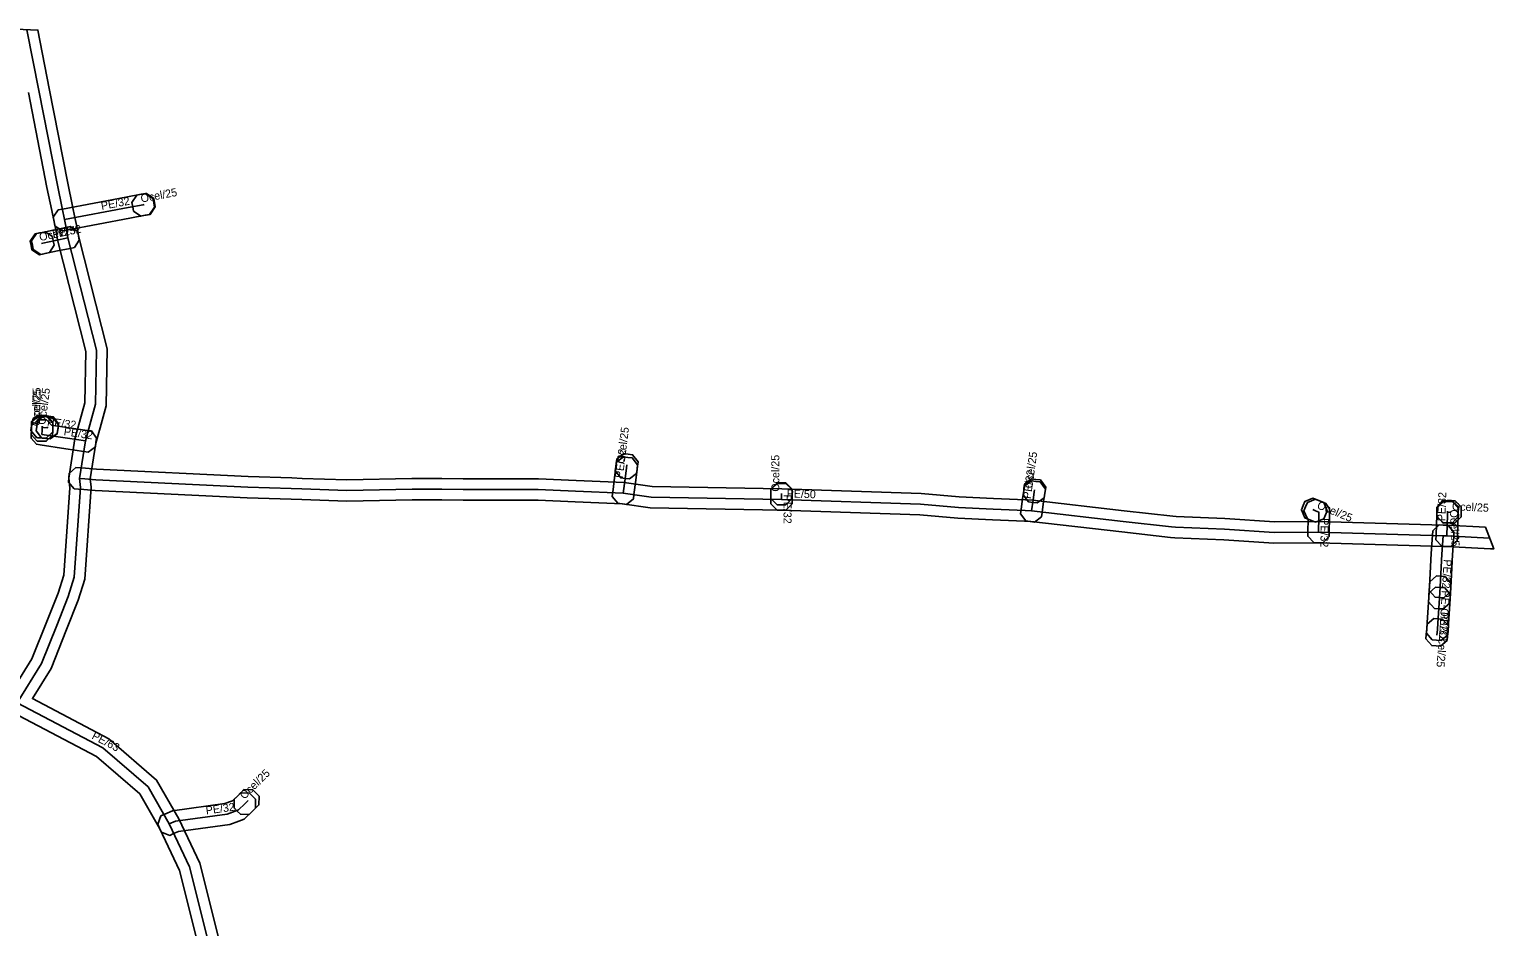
# Model space of a CAD drawing. Extents: x -678368 to -678136, y -1057358 to -1057053.
# Drawn here: x -678273.5 to -678136.2, y -1057136.9 to -1057052.8 of the extents above; entities that cross this region are included whole.
import ezdxf

# ---------------------------------------------------------------- set-up
doc = ezdxf.new("R2010")
doc.units = 0
for name, color, linetype in [('1', 7, 'Continuous'), ('24', 7, 'Continuous'), ('28', 7, 'Continuous'), ('30', 7, 'Continuous')]:
    doc.layers.add(name, color=color, linetype=linetype)

msp = doc.modelspace()

# ---------------------------------------------------------------- linework, layer by layer
at = {"layer": '1'}
for points in [[(-678274.76, -1057052.79), (-678272.71, -1057052.87), (-678271.64, -1057058.33), (-678269.9, -1057067.22), (-678269.45, -1057069.36), (-678269.23, -1057070.42), (-678268.99, -1057071.55), (-678268.91, -1057072.16), (-678266.21, -1057082.76), (-678266.31, -1057088.09), (-678266.88, -1057090.14), (-678267.27, -1057091.59), (-678267.8, -1057094.94), (-678267.72, -1057095.73), (-678268.31, -1057104.33), (-678268.92, -1057106.31), (-678270.01, -1057109.06), (-678271.47, -1057112.71), (-678273.22, -1057115.53), (-678266.06, -1057119.31), (-678261.58, -1057123.18), (-678259.5, -1057126.82), (-678257.54, -1057130.97), (-678255.66, -1057138.42)], [(-678275.49, -1057115.39), (-678273.27, -1057111.81), (-678271.87, -1057108.32), (-678270.8, -1057105.65), (-678270.29, -1057103.97), (-678269.72, -1057095.77), (-678269.82, -1057094.88), (-678269.23, -1057091.17), (-678268.8, -1057089.61), (-678268.31, -1057087.8), (-678268.21, -1057083), (-678270.87, -1057072.54), (-678270.96, -1057071.89), (-678271.19, -1057070.83), (-678271.41, -1057069.77), (-678271.86, -1057067.62), (-678273.6, -1057058.71)], [(-678257.62, -1057138.86), (-678259.44, -1057131.65), (-678261.28, -1057127.74), (-678263.14, -1057124.47), (-678267.2, -1057120.97), (-678275.11, -1057116.8)]]:
    msp.add_lwpolyline(points, dxfattribs=at)
for points in [[(-678262.25, -1057070.15), (-678262.65, -1057070.23), (-678264.08, -1057070.49), (-678270.03, -1057071.61), (-678270.43, -1057071.69), (-678271.11, -1057071.22), (-678271.19, -1057070.81), (-678271.27, -1057070.4), (-678270.8, -1057069.72), (-678270.39, -1057069.64), (-678264.45, -1057068.53), (-678263.02, -1057068.26), (-678262.61, -1057068.18), (-678261.93, -1057068.65), (-678261.85, -1057069.06), (-678261.78, -1057069.47)], [(-678263.43, -1057068.34), (-678263.02, -1057068.26), (-678262.94, -1057068.25), (-678262.54, -1057068.17), (-678261.85, -1057068.64), (-678261.78, -1057069.04), (-678261.7, -1057069.45), (-678262.17, -1057070.14), (-678262.57, -1057070.21), (-678262.65, -1057070.23), (-678263.06, -1057070.3), (-678263.74, -1057069.83), (-678263.82, -1057069.43), (-678263.9, -1057069.02)], [(-678271.63, -1057073.73), (-678272.04, -1057073.81), (-678272.16, -1057073.84), (-678272.57, -1057073.92), (-678273.26, -1057073.47), (-678273.34, -1057073.06), (-678273.43, -1057072.66), (-678272.97, -1057071.97), (-678272.57, -1057071.88), (-678272.44, -1057071.86), (-678272.04, -1057071.77), (-678271.34, -1057072.23), (-678271.26, -1057072.63), (-678271.18, -1057073.04)], [(-678269.28, -1057073.25), (-678269.69, -1057073.33), (-678270.87, -1057073.57), (-678272.04, -1057073.81), (-678272.44, -1057073.9), (-678273.14, -1057073.44), (-678273.22, -1057073.04), (-678273.3, -1057072.63), (-678272.85, -1057071.94), (-678272.44, -1057071.86), (-678271.28, -1057071.61), (-678270.09, -1057071.37), (-678269.69, -1057071.29), (-678268.99, -1057071.74), (-678268.91, -1057072.15), (-678268.83, -1057072.55)], [(-678272.2, -1057089.11), (-678272.09, -1057089.12), (-678272.07, -1057089.1), (-678271.66, -1057089.17), (-678271.25, -1057089.24), (-678270.77, -1057089.91), (-678270.84, -1057090.32), (-678270.84, -1057090.33), (-678270.91, -1057090.72), (-678271.55, -1057091.2), (-678271.95, -1057091.15), (-678272.31, -1057091.11), (-678272.43, -1057091.09), (-678272.84, -1057091.05), (-678273.36, -1057090.39), (-678273.31, -1057089.98), (-678273.26, -1057089.57), (-678272.61, -1057089.06)], [(-678271.89, -1057089.4), (-678271.42, -1057089.9), (-678269.79, -1057090.14), (-678268.1, -1057090.39), (-678267.69, -1057090.45), (-678267.2, -1057091.12), (-678267.26, -1057091.53), (-678267.32, -1057091.94), (-678267.99, -1057092.43), (-678268.4, -1057092.37), (-678270.09, -1057092.12), (-678272.48, -1057091.76), (-678272.85, -1057091.7), (-678273.34, -1057091.13), (-678273.33, -1057090.75), (-678273.32, -1057090.37), (-678273.31, -1057089.96), (-678272.71, -1057089.39), (-678272.3, -1057089.4)], [(-678273.33, -1057090.78), (-678273.32, -1057090.37), (-678273.32, -1057090.08), (-678273.31, -1057089.66), (-678272.7, -1057089.09), (-678272.29, -1057089.1), (-678271.88, -1057089.11), (-678271.31, -1057089.71), (-678271.32, -1057090.13), (-678271.32, -1057090.42), (-678271.33, -1057090.83), (-678271.93, -1057091.41), (-678272.35, -1057091.4), (-678272.76, -1057091.39)], [(-678273.32, -1057090.5), (-678273.32, -1057090.08), (-678273.31, -1057089.97), (-678273.31, -1057089.56), (-678272.71, -1057088.98), (-678272.3, -1057088.99), (-678271.88, -1057089), (-678271.31, -1057089.59), (-678271.31, -1057090.01), (-678271.32, -1057090.12), (-678271.32, -1057090.53), (-678271.92, -1057091.11), (-678272.33, -1057091.1), (-678272.75, -1057091.09)], [(-678272.87, -1057090.43), (-678272.82, -1057090.02), (-678272.8, -1057089.92), (-678272.75, -1057089.51), (-678272.09, -1057089.01), (-678271.68, -1057089.06), (-678271.27, -1057089.12), (-678270.76, -1057089.77), (-678270.82, -1057090.19), (-678270.83, -1057090.29), (-678270.89, -1057090.7), (-678271.55, -1057091.2), (-678271.96, -1057091.15), (-678272.37, -1057091.09)], [(-678216.49, -1057093.62), (-678216.54, -1057094.03), (-678216.67, -1057095.07), (-678216.84, -1057096.41), (-678216.89, -1057096.82), (-678217.54, -1057097.33), (-678217.95, -1057097.28), (-678218.36, -1057097.23), (-678218.87, -1057096.58), (-678218.82, -1057096.17), (-678218.66, -1057094.83), (-678218.53, -1057093.78), (-678218.48, -1057093.37), (-678217.82, -1057092.86), (-678217.41, -1057092.92), (-678217, -1057092.97)], [(-678218.58, -1057094.2), (-678218.53, -1057093.78), (-678218.49, -1057093.49), (-678218.44, -1057093.08), (-678217.79, -1057092.57), (-678217.37, -1057092.62), (-678216.96, -1057092.67), (-678216.45, -1057093.33), (-678216.51, -1057093.74), (-678216.54, -1057094.03), (-678216.59, -1057094.44), (-678217.25, -1057094.95), (-678217.66, -1057094.9), (-678218.07, -1057094.85)], [(-678137.01, -1057099.48), (-678136.24, -1057101.51), (-678136.55, -1057101.51), (-678140.66, -1057101.27), (-678140.99, -1057101.28), (-678152.68, -1057100.92), (-678156.84, -1057100.96), (-678161.54, -1057100.66), (-678166.12, -1057100.47), (-678166.53, -1057100.44), (-678171.1, -1057099.91), (-678179.64, -1057098.94), (-678180.22, -1057098.91), (-678183.21, -1057098.77), (-678186.48, -1057098.61), (-678190.04, -1057098.32), (-678203.04, -1057097.86), (-678215.3, -1057097.64), (-678217.92, -1057097.29), (-678222.35, -1057097.1), (-678225.82, -1057096.95), (-678229.3, -1057096.93), (-678232.85, -1057096.93), (-678234.85, -1057096.91), (-678237.62, -1057096.89), (-678243.76, -1057097.02), (-678247.98, -1057096.88), (-678248.98, -1057096.85), (-678253.08, -1057096.72), (-678267.34, -1057096.03), (-678268.4, -1057095.95), (-678268.89, -1057095.91), (-678269.3, -1057095.88), (-678269.84, -1057095.25), (-678269.81, -1057094.83), (-678269.78, -1057094.42), (-678269.15, -1057093.88), (-678268.73, -1057093.91), (-678268.25, -1057093.95), (-678267.22, -1057094.03), (-678253, -1057094.72), (-678248.91, -1057094.85), (-678247.92, -1057094.89), (-678243.74, -1057095.02), (-678237.64, -1057094.89), (-678234.83, -1057094.91), (-678232.84, -1057094.93), (-678229.3, -1057094.93), (-678225.78, -1057094.95), (-678222.26, -1057095.1), (-678217.74, -1057095.29), (-678215.14, -1057095.64), (-678202.98, -1057095.86), (-678189.92, -1057096.32), (-678186.35, -1057096.61), (-678183.12, -1057096.77), (-678180.12, -1057096.91), (-678179.48, -1057096.94), (-678170.88, -1057097.93), (-678166.33, -1057098.45), (-678166, -1057098.47), (-678161.44, -1057098.66), (-678156.78, -1057098.96), (-678152.66, -1057098.92), (-678140.99, -1057099.28), (-678140.62, -1057099.27)], [(-678178.26, -1057095.89), (-678178.32, -1057096.3), (-678178.43, -1057097.07), (-678178.57, -1057098.08), (-678178.63, -1057098.49), (-678179.29, -1057098.99), (-678179.7, -1057098.93), (-678180.11, -1057098.87), (-678180.61, -1057098.21), (-678180.55, -1057097.8), (-678180.41, -1057096.79), (-678180.3, -1057096.02), (-678180.24, -1057095.61), (-678179.58, -1057095.11), (-678179.17, -1057095.17), (-678178.76, -1057095.23)], [(-678180.36, -1057096.43), (-678180.3, -1057096.02), (-678180.28, -1057095.84), (-678180.22, -1057095.43), (-678179.56, -1057094.93), (-678179.15, -1057094.99), (-678178.74, -1057095.04), (-678178.24, -1057095.71), (-678178.3, -1057096.11), (-678178.32, -1057096.29), (-678178.38, -1057096.71), (-678179.04, -1057097.2), (-678179.45, -1057097.15), (-678179.86, -1057097.09)], [(-678204.01, -1057096.77), (-678204.01, -1057096.36), (-678204.01, -1057096.31), (-678204.01, -1057095.9), (-678203.42, -1057095.31), (-678203.01, -1057095.31), (-678202.6, -1057095.31), (-678202.01, -1057095.9), (-678202.01, -1057096.31), (-678202.01, -1057096.36), (-678202.01, -1057096.77), (-678202.6, -1057097.36), (-678203.01, -1057097.36), (-678203.42, -1057097.36)], [(-678202.01, -1057095.95), (-678202.01, -1057096.36), (-678202.01, -1057096.74), (-678202.01, -1057096.86), (-678202.01, -1057097.27), (-678202.6, -1057097.86), (-678203.01, -1057097.86), (-678203.42, -1057097.86), (-678204.01, -1057097.27), (-678204.01, -1057096.86), (-678204.01, -1057096.74), (-678204.01, -1057096.36), (-678204.01, -1057095.95), (-678203.42, -1057095.36), (-678203.01, -1057095.36), (-678202.6, -1057095.36)], [(-678152.94, -1057099.01), (-678153.33, -1057098.85), (-678153.57, -1057098.75), (-678153.95, -1057098.59), (-678154.27, -1057097.83), (-678154.11, -1057097.44), (-678153.95, -1057097.06), (-678153.19, -1057096.74), (-678152.81, -1057096.9), (-678152.56, -1057097), (-678152.18, -1057097.16), (-678151.86, -1057097.92), (-678152.02, -1057098.31), (-678152.18, -1057098.69)], [(-678153.67, -1057099.9), (-678153.65, -1057098.72), (-678153.71, -1057098.69), (-678154.03, -1057097.93), (-678153.87, -1057097.55), (-678153.71, -1057097.16), (-678152.95, -1057096.84), (-678152.57, -1057097), (-678152.26, -1057097.12), (-678151.97, -1057097.24), (-678151.64, -1057097.76), (-678151.64, -1057098.07), (-678151.65, -1057098.55), (-678151.67, -1057099.94), (-678151.68, -1057100.35), (-678152.27, -1057100.93), (-678152.69, -1057100.92), (-678153.1, -1057100.91), (-678153.68, -1057100.32)], [(-678141.66, -1057100.65), (-678141.64, -1057100.23), (-678141.6, -1057099.22), (-678141.57, -1057098.34), (-678141.56, -1057098.05), (-678141.55, -1057097.64), (-678140.95, -1057097.06), (-678140.53, -1057097.07), (-678140.12, -1057097.08), (-678139.55, -1057097.69), (-678139.56, -1057098.1), (-678139.57, -1057098.4), (-678139.6, -1057099.29), (-678139.64, -1057100.31), (-678139.66, -1057100.72), (-678140.27, -1057101.29), (-678140.68, -1057101.27), (-678141.09, -1057101.25)], [(-678139.59, -1057097.51), (-678139.56, -1057097.93), (-678139.56, -1057098.02), (-678139.54, -1057098.44), (-678140.09, -1057099.05), (-678140.51, -1057099.07), (-678140.92, -1057099.09), (-678141.54, -1057098.54), (-678141.56, -1057098.13), (-678141.56, -1057098.03), (-678141.58, -1057097.62), (-678141.03, -1057097), (-678140.61, -1057096.98), (-678140.2, -1057096.96)], [(-678140.93, -1057097.06), (-678140.77, -1057097.06), (-678140.7, -1057096.99), (-678140.28, -1057096.99), (-678139.87, -1057096.99), (-678139.28, -1057097.57), (-678139.28, -1057097.99), (-678139.28, -1057098.09), (-678139.28, -1057098.51), (-678139.59, -1057098.81), (-678139.9, -1057099.1), (-678140.32, -1057099.09), (-678140.6, -1057099.07), (-678141.02, -1057099.06), (-678141.58, -1057098.45), (-678141.56, -1057098.03), (-678141.54, -1057097.62)], [(-678139.97, -1057099.93), (-678139.99, -1057100.34), (-678140.09, -1057102.06), (-678140.24, -1057104.52), (-678140.27, -1057105.12), (-678140.3, -1057105.53), (-678140.92, -1057106.08), (-678141.33, -1057106.06), (-678141.74, -1057106.03), (-678142.29, -1057105.41), (-678142.27, -1057105), (-678142.23, -1057104.4), (-678142.09, -1057101.95), (-678141.99, -1057100.22), (-678141.96, -1057099.81), (-678141.34, -1057099.26), (-678140.93, -1057099.28), (-678140.52, -1057099.31)], [(-678140.25, -1057104.71), (-678140.27, -1057105.12), (-678140.33, -1057106.17), (-678140.36, -1057106.58), (-678140.98, -1057107.13), (-678141.39, -1057107.11), (-678141.8, -1057107.08), (-678142.35, -1057106.46), (-678142.33, -1057106.05), (-678142.27, -1057105), (-678142.24, -1057104.59), (-678141.62, -1057104.04), (-678141.21, -1057104.06), (-678140.8, -1057104.08)], [(-678140.31, -1057105.75), (-678140.33, -1057106.17), (-678140.47, -1057108.53), (-678140.52, -1057109.14), (-678140.55, -1057109.55), (-678141.18, -1057110.09), (-678141.59, -1057110.06), (-678142.01, -1057110.03), (-678142.55, -1057109.4), (-678142.51, -1057108.99), (-678142.47, -1057108.39), (-678142.33, -1057106.05), (-678142.31, -1057105.64), (-678141.69, -1057105.09), (-678141.27, -1057105.11), (-678140.86, -1057105.13)], [(-678140.49, -1057108.73), (-678140.52, -1057109.14), (-678140.56, -1057109.68), (-678140.59, -1057110.09), (-678141.22, -1057110.63), (-678141.63, -1057110.6), (-678142.05, -1057110.56), (-678142.59, -1057109.94), (-678142.56, -1057109.52), (-678142.51, -1057108.99), (-678142.48, -1057108.57), (-678141.85, -1057108.04), (-678141.44, -1057108.07), (-678141.03, -1057108.1)], [(-678252.31, -1057125.81), (-678252.6, -1057126.1), (-678253.36, -1057126.85), (-678253.86, -1057127.03), (-678254.71, -1057127.34), (-678259.54, -1057127.99), (-678259.98, -1057128.19), (-678260.35, -1057128.36), (-678261.13, -1057128.07), (-678261.3, -1057127.69), (-678261.47, -1057127.32), (-678261.18, -1057126.54), (-678260.8, -1057126.37), (-678260.1, -1057126.05), (-678255.19, -1057125.38), (-678254.55, -1057125.15), (-678254.46, -1057125.12), (-678254, -1057124.67), (-678253.71, -1057124.38), (-678252.88, -1057124.39), (-678252.59, -1057124.68), (-678252.3, -1057124.98)], [(-678254.3, -1057124.96), (-678254, -1057124.67), (-678253.69, -1057124.36), (-678253.39, -1057124.07), (-678252.57, -1057124.08), (-678252.28, -1057124.38), (-678251.98, -1057124.67), (-678251.99, -1057125.5), (-678252.29, -1057125.79), (-678252.6, -1057126.1), (-678252.9, -1057126.39), (-678253.73, -1057126.38), (-678254.02, -1057126.08), (-678254.31, -1057125.79)]]:
    msp.add_lwpolyline(points, close=True, dxfattribs=at)
at = {"layer": '24'}
for points in [[(-678273.74, -1057052.83), (-678272.62, -1057058.52), (-678270.88, -1057067.42), (-678270.43, -1057069.57), (-678270.21, -1057070.63), (-678269.98, -1057071.72), (-678269.89, -1057072.35), (-678267.21, -1057082.88), (-678267.31, -1057087.95), (-678267.84, -1057089.88), (-678268.25, -1057091.38), (-678268.81, -1057094.91), (-678268.72, -1057095.75), (-678269.3, -1057104.15), (-678269.86, -1057105.98), (-678270.94, -1057108.69), (-678272.37, -1057112.26), (-678274.64, -1057115.92), (-678266.63, -1057120.14), (-678262.36, -1057123.82), (-678260.39, -1057127.28), (-678258.49, -1057131.31), (-678256.64, -1057138.64)], [(-678262.84, -1057069.24), (-678264.26, -1057069.51), (-678270.21, -1057070.63)], [(-678262.84, -1057069.24), (-678262.76, -1057069.23)], [(-678272.24, -1057072.83), (-678272.37, -1057072.86)], [(-678269.89, -1057072.35), (-678271.07, -1057072.59), (-678272.24, -1057072.83)], [(-678268.25, -1057091.38), (-678269.94, -1057091.13), (-678272.33, -1057090.77), (-678272.32, -1057090.4)], [(-678272.32, -1057090.1), (-678272.31, -1057089.99)], [(-678271.82, -1057090.16), (-678271.83, -1057090.16), (-678272.19, -1057090.12), (-678272.32, -1057090.1)], [(-678272.32, -1057090.4), (-678272.32, -1057090.1)], [(-678271.82, -1057090.16), (-678271.81, -1057090.05)], [(-678217.54, -1057093.91), (-678217.5, -1057093.61)], [(-678136.63, -1057100.5), (-678140.64, -1057100.27), (-678140.99, -1057100.28), (-678152.67, -1057099.92), (-678156.81, -1057099.96), (-678161.49, -1057099.66), (-678166.06, -1057099.47), (-678166.43, -1057099.44), (-678170.99, -1057098.92), (-678179.56, -1057097.94), (-678180.17, -1057097.91), (-678183.17, -1057097.77), (-678186.42, -1057097.61), (-678189.98, -1057097.32), (-678203.01, -1057096.86), (-678215.22, -1057096.64), (-678217.83, -1057096.29), (-678222.3, -1057096.1), (-678225.8, -1057095.95), (-678229.3, -1057095.93), (-678232.84, -1057095.93), (-678234.84, -1057095.91), (-678237.63, -1057095.89), (-678243.75, -1057096.02), (-678247.95, -1057095.88), (-678248.95, -1057095.85), (-678253.04, -1057095.72), (-678267.28, -1057095.03), (-678268.32, -1057094.95), (-678268.81, -1057094.91)], [(-678217.54, -1057093.91), (-678217.66, -1057094.95), (-678217.83, -1057096.29)], [(-678203.01, -1057096.36), (-678203.01, -1057096.31)], [(-678203.01, -1057096.36), (-678203.01, -1057096.74), (-678203.01, -1057096.86)], [(-678179.31, -1057096.16), (-678179.42, -1057096.93), (-678179.56, -1057097.94)], [(-678179.31, -1057096.16), (-678179.29, -1057095.98)], [(-678152.95, -1057097.93), (-678153.19, -1057097.82)], [(-678152.95, -1057097.93), (-678152.64, -1057098.05), (-678152.65, -1057098.53), (-678152.67, -1057099.92)], [(-678140.64, -1057100.27), (-678140.6, -1057099.25), (-678140.57, -1057098.37), (-678140.56, -1057098.07)], [(-678140.56, -1057097.98), (-678140.56, -1057098.07)], [(-678140.99, -1057100.28), (-678141.09, -1057102), (-678141.23, -1057104.46), (-678141.27, -1057105.06)], [(-678141.33, -1057106.11), (-678141.47, -1057108.46), (-678141.52, -1057109.06)], [(-678141.52, -1057109.06), (-678141.56, -1057109.6)], [(-678253.3, -1057125.39), (-678252.99, -1057125.08)], [(-678253.3, -1057125.39), (-678253.91, -1057125.98), (-678254.2, -1057126.09), (-678254.95, -1057126.36), (-678259.82, -1057127.02), (-678260.39, -1057127.28)]]:
    msp.add_lwpolyline(points, dxfattribs=at)
at = {"layer": '28'}
for points in [[(-678140.56, -1057098.07), (-678140.28, -1057098.09), (-678140.28, -1057097.99)], [(-678141.27, -1057105.06), (-678141.33, -1057106.11)]]:
    msp.add_lwpolyline(points, dxfattribs=at)

# ---------------------------------------------------------------- texts
at = {"layer": '30'}
for s, rotation, p in [('Ocel/25', 10.6197, (-678263, -1057069.04)), ('PE/32', 10.6301, (-678266.72, -1057069.73)), ('Ocel/25', 11.6593, (-678272.5, -1057072.65)), ('PE/32', 11.6446, (-678271.27, -1057072.39)), ('Ocel/25', 88.9949, (-678272.51, -1057089.84)), ('Ocel/25', 88.6314, (-678272.52, -1057090)), ('Ocel/25', 82.3332, (-678272.02, -1057089.9)), ('PE/32', 352.9716, (-678271.87, -1057089.93)), ('PE/32', 351.5079, (-678270.32, -1057090.84)), ('Ocel/25', 82.8511, (-678217.72, -1057093.56)), ('PE/32', 82.9277, (-678217.88, -1057094.9)), ('Ocel/25', 90, (-678203.21, -1057096.14)), ('Ocel/25', 82.0928, (-678179.5, -1057095.87)), ('PE/32', 82.0449, (-678179.64, -1057096.85)), ('PE/32', 270, (-678202.81, -1057096.41)), ('PE/50', 357.9781, (-678202.53, -1057096.67)), ('PE/32', 87.7301, (-678140.79, -1057098.92)), ('Ocel/25', 337.6317, (-678152.87, -1057097.68)), ('Ocel/25', 272.9508, (-678140.36, -1057097.83)), ('Ocel/25', 357.5194, (-678140.17, -1057097.88)), ('PE/32', 269.0926, (-678152.45, -1057098.62)), ('PE/32', 266.6431, (-678140.93, -1057102.47)), ('PE-O/32', 266.6175, (-678141.1, -1057105.38)), ('PE/32', 266.6421, (-678141.22, -1057107.39)), ('Ocel/25', 265.6177, (-678141.34, -1057109.13)), ('PE/63', 332.2179, (-678267.72, -1057119.26)), ('Ocel/25', 44.4455, (-678253.35, -1057125.03)), ('PE/32', 7.7195, (-678256.92, -1057126.4))]:
    msp.add_text(s, height=0.75, rotation=rotation, dxfattribs=at).set_placement(p)

doc.saveas('drawing.dxf')
